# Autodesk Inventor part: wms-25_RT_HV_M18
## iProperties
Shininess: 20.0
Length Units: 11269
Angle Units: 11279
Time Units: 11290
Mass Units: 11283
Length Display Precision: 2
Angle Display Precision: 2
Part Number: wms-25_RT_HV_M18
Material: Nichtrostender Stahl - 440C
Document SubType Name: Modellieren
Description: wms-25 Sensoren
Checked By: Alves
Created: 2005-08
Designer: Ohle
Manufacturer: Standard
Standards Organization: Custom
Density: 0.0
Volumn: 0.0
Area: 0.0
PropertySet Name: Model Information
Control State: 0
Master: False
Checked Out: False
Last Check In By: Tanck
Last Check In Date: 2005-08-09
BESTELLNUMMER: wms-25/RT/HV/M18
ME: ST
Title: wms- Sensoren
Author: Ohle
Comments: keine Bemerkung
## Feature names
1. Grundkörper wms-25 [Revolution]
2. Pole [Extrusion]
3. Rundung Pole [Fillet]
4. Verdrehsicherung [Extrusion]
